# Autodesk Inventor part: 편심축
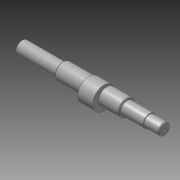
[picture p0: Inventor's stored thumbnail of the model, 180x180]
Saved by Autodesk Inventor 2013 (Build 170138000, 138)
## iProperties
Created: 2016-05
Part Number: 편심축
Document SubType Name: Modeling
Designer: mduedu
Density: 7.86 g/cm^3
Material: 강철, 연강
Author: mduedu
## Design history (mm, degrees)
sketch "스케치1"
  geometry: L1 (-40.5, 11)-(-40.5, 8.5); L2 (45.5, 11)-(45.5, 8.5); L3 (-95.5, 0)-(95.5, 0); L4 (-40.5, 11)-(45.5, 11); L5 (45.5, 11)-(45.5, 8.5); L6 (-40.5, 11)-(-40.5, 8.5); L7 (-40.5, 8.5)-(-95.5, 8.5); L8 (-95.5, 8.5)-(-95.5, 0); L9 (45.5, 8.5)-(75.5, 8.5); L10 (95.5, 7.5)-(95.5, 0); L11 (75.5, 8.5)-(75.5, 7.5); L12 (75.5, 7.5)-(95.5, 7.5); 1 further point
  constraints: 24 end point, 9 perpendicular, 2 midpoint, 1 collinear, 1 horizontal
  dimensions: "d0" = 22 diameter of L4 L3; "d1" = 17 diameter of L7 L3; "d2" = 55 distance between parallel lines of L8 L1; "d3" = 50 distance between parallel lines of L10 L2; "d4" = 15 diameter of L12 L3; "d5" = 20 distance between parallel lines of L10 L11; "d29" = 86 distance of L1.start L2.start
revolve "회전1" stored, may be unused: angle "d6" = 90 deg
node "작업 평면7"
node "작업 평면9"
sketch "스케치2"
  geometry: C1 r 11 at (0, 0); C2 r 15 at (0, -4); C3 r 11 at (0, 0); 2 further points
  constraints: 3 centre point, 2 coincident, 1 concentric, 1 vertical alignment
  dimensions: "d9" = 4 distance of point (0, 0) C2.centre; "d10" = 30 diameter of C2
extrude "돌출1" join sketch "스케치2" stored distance "d11" = 20; taper "d12" = 0 deg
chamfer "모따기1" distance "d17" = 1; stored, may be unused: second distance "d18" = 2, angle "d19" = 45 deg
node "작업 평면4"
sketch "스케치4"
  geometry: L1 (-10, -6.5)-(-10, 6.5) reference; L2 (-5, 2.5)-(5, 2.5); L3 (5, -2.5)-(-5, -2.5); A1 r 2.5 centre (5, 0) between (5, -2.5) and (5, 2.5); A2 r 2.5 centre (-5, 0) between (-5, 2.5) and (-5, -2.5); 2 further points
  constraints: 4 end point, 4 point on circle, 4 tangent, 2 centre point, 1 horizontal alignment, 1 midpoint, 1 parallel, 1 perpendicular
  dimensions: "d20" = 5 distance between parallel lines of L3 L2; "d21" = 15 dimension on A1 A2; "d22" = 2.5 distance edge to line of A2 L1
extrude "돌출3" cut sketch "스케치4" distance "d23" = 3; taper "d24" = 0 deg
node "작업 평면5"
sketch "스케치5"
  geometry: L1 (27.5, 7.5)-(27.5, -7.5) reference; L2 (27.5, 2.5)-(10, 2.5); L3 (10, -2.5)-(27.5, -2.5); A1 r 2.5 centre (10, 0) between (10, 2.5) and (10, -2.5); 2 further points
  constraints: 4 end point, 2 perpendicular, 2 point on circle, 2 point on line, 2 tangent, 1 centre point, 1 horizontal alignment, 1 midpoint
  dimensions: "d25" = 5 distance between parallel lines of L3 L2; "d26" = 20 dimension on A1 L1
extrude "돌출4" cut sketch "스케치5" distance "d27" = 3; taper "d28" = 0 deg
hole "구멍1" diameter "d34" = 3.242; stored, may be unused: countersink angle "d38" = 90 deg, drill point angle "d40" = 118 deg; dims "d35" = 9, "d36" = 4, "d37" = 2, "d39" = 11, "d43" = 10, "d44" = 10
node "솔리드1"
other parameters: "d31" = -37
